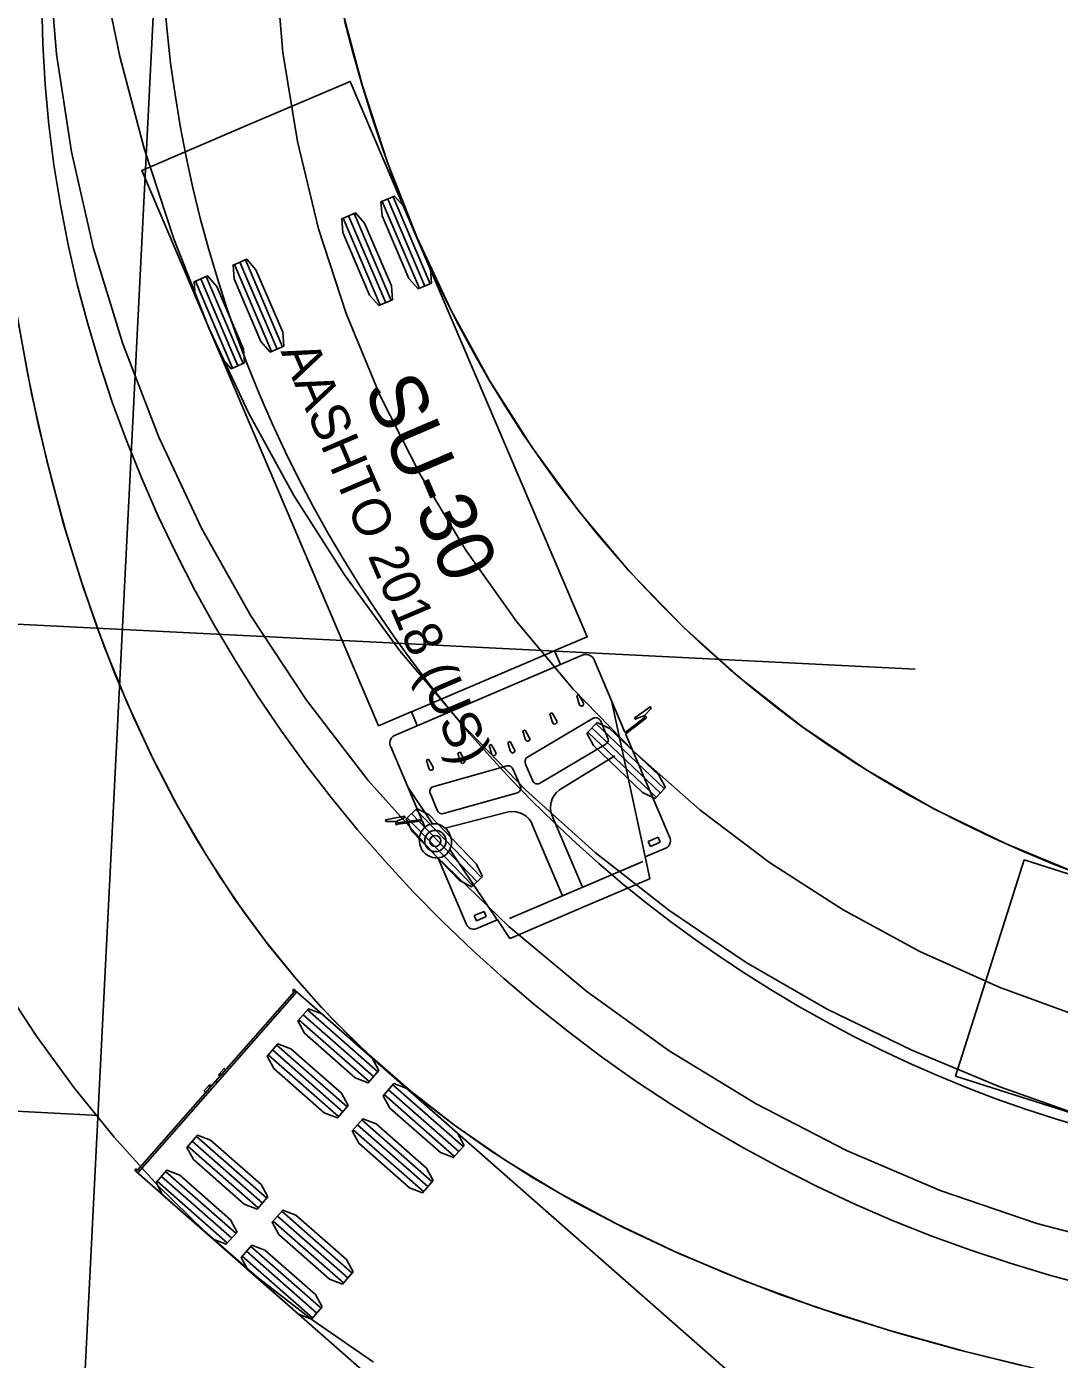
# Model space of a CAD drawing. Extents: x 260275 to 261282, y 610916 to 614143.
# Drawn here: x 261018.91 to 261055.33, y 611607.94 to 611654.93 of the extents above; entities that cross this region are included whole.
import ezdxf

# ---------------------------------------------------------------- set-up
doc = ezdxf.new("R2010")
doc.units = 0
for name, color, linetype in [('DR_P_Ditch', 7, 'Continuous'), ('GE_X_Alignment', 7, 'Continuous'), ('UT_X_Water_Cells', 7, 'Continuous')]:
    doc.layers.add(name, color=color, linetype=linetype)

msp = doc.modelspace()

# ---------------------------------------------------------------- linework, layer by layer
at = {"layer": 'DR_P_Ditch'}
msp.add_line((260830.144, 611626.697), (261021.455, 611616.54), dxfattribs=at)
at = {"layer": 'GE_X_Alignment'}
msp.add_line((260986.249, 610915.954), (261148.276, 614142.838), dxfattribs=at)
at = {"layer": 'UT_X_Water_Cells'}
for p, q in [((261032.763, 611645.701), (261031.455, 611648.767)), ((261032.955, 611645.783), (261031.646, 611648.849)), ((261033.146, 611645.865), (261031.838, 611648.931)), ((261031.767, 611645.276), (261030.458, 611648.342)), ((261031.383, 611645.113), (261030.075, 611648.178)), ((261031.575, 611645.194), (261030.267, 611648.26)), ((261027.551, 611643.477), (261026.243, 611646.543)), ((261027.743, 611643.559), (261026.434, 611646.625)), ((261027.934, 611643.641), (261026.626, 611646.706)), ((261026.172, 611642.888), (261024.863, 611645.954)), ((261026.363, 611642.97), (261025.055, 611646.036)), ((261026.555, 611643.052), (261025.246, 611646.118)), ((261050.252, 611632.276), (261008.305, 611634.382)), ((261032.48, 611630.772), (261037.531, 611632.928)), ((261032.688, 611630.283), (261037.739, 611632.439)), ((261038.314, 611631.336), (261038.39, 611631.368)), ((261038.39, 611631.368), (261038.54, 611631.107)), ((261038.399, 611631.046), (261038.314, 611631.336)), ((261039.537, 611631.167), (261040.728, 611625.664)), ((261036.571, 611629.174), (261038.911, 611630.555)), ((261037.369, 611630.704), (261037.445, 611630.736)), ((261037.46, 611630.402), (261037.369, 611630.704)), ((261037.445, 611630.736), (261037.602, 611630.462)), ((261039.157, 611630.44), (261039.399, 611629.873)), ((261036.413, 611630.098), (261036.489, 611630.13)), ((261036.498, 611629.808), (261036.413, 611630.098)), ((261036.489, 611630.13), (261036.64, 611629.868)), ((261041.119, 611627.76), (261038.704, 611630.058)), ((261041.262, 611627.91), (261038.848, 611630.209)), ((261041.406, 611628.061), (261038.991, 611630.359)), ((261035.221, 611629.589), (261035.296, 611629.621)), ((261035.305, 611629.299), (261035.221, 611629.589)), ((261035.296, 611629.621), (261035.447, 611629.359)), ((261035.883, 611629.688), (261035.959, 611629.721)), ((261035.967, 611629.398), (261035.883, 611629.688)), ((261035.959, 611629.721), (261036.109, 611629.459)), ((261039.339, 611629.628), (261036.999, 611628.247)), ((261033.011, 611629.073), (261033.087, 611629.105)), ((261033.096, 611628.783), (261033.011, 611629.073)), ((261033.087, 611629.105), (261033.238, 611628.843)), ((261034.121, 611629.318), (261034.197, 611629.35)), ((261034.206, 611629.028), (261034.121, 611629.318)), ((261034.197, 611629.35), (261034.348, 611629.089)), ((261037.707, 611628.02), (261039.654, 611629.226)), ((261035.854, 611628.868), (261033.238, 611628.134)), ((261036.315, 611628.174), (261036.073, 611628.742)), ((261036.753, 611628.361), (261036.51, 611628.928)), ((261032.363, 611628.105), (261033.23, 611626.821)), ((261033.15, 611627.877), (261033.393, 611627.309)), ((261033.611, 611627.183), (261036.227, 611627.917)), ((261034.798, 611624.781), (261032.487, 611627.184)), ((261034.948, 611624.926), (261032.638, 611627.329)), ((261035.901, 611627.249), (261033.672, 611626.675)), ((261034.647, 611624.637), (261032.337, 611627.04)), ((261037.816, 611624.288), (261036.769, 611626.742)), ((261038.52, 611624.589), (261037.473, 611627.043)), ((261040.834, 611626.205), (261041.183, 611626.354)), ((261040.911, 611626.027), (261040.834, 611626.205)), ((261041.183, 611626.354), (261041.259, 611626.175)), ((261033.837, 611625.921), (261035.512, 611623.438)), ((261041.259, 611626.175), (261040.911, 611626.027)), ((261033.424, 611625.619), (261034.414, 611623.299)), ((261035.943, 611623.489), (261040.638, 611625.492)), ((261035.048, 611623.736), (261034.699, 611623.587)), ((261034.699, 611623.587), (261034.776, 611623.409)), ((261034.776, 611623.409), (261035.124, 611623.557)), ((261035.124, 611623.557), (261035.048, 611623.736)), ((261022.829, 611614.518), (261028.44, 611620.904)), ((261031.149, 611617.913), (261028.67, 611620.091)), ((261031.3, 611618.085), (261028.821, 611620.264)), ((261030.998, 611617.741), (261028.518, 611619.919)), ((261029.909, 611616.502), (261027.429, 611618.68)), ((261030.06, 611616.674), (261027.581, 611618.852)), ((261030.211, 611616.846), (261027.732, 611619.024)), ((261025.753, 611617.952), (261025.407, 611617.559)), ((261025.582, 611617.757), (261025.635, 611617.711)), ((261025.757, 611617.957), (261025.932, 611618.156)), ((261025.231, 611617.358), (261025.406, 611617.558)), ((261034.003, 611615.101), (261031.523, 611617.279)), ((261034.154, 611615.273), (261031.675, 611617.451)), ((261034.305, 611615.445), (261031.826, 611617.623)), ((261033.216, 611614.206), (261030.737, 611616.384)), ((261032.913, 611613.861), (261030.434, 611616.04)), ((261033.065, 611614.034), (261030.586, 611616.212)), ((261027.081, 611613.284), (261024.602, 611615.462)), ((261027.233, 611613.456), (261024.754, 611615.634)), ((261027.384, 611613.628), (261024.905, 611615.806)), ((261026.295, 611612.389), (261023.816, 611614.567)), ((261025.992, 611612.044), (261023.513, 611614.222)), ((261026.144, 611612.216), (261023.664, 611614.395)), ((261030.389, 611610.988), (261027.91, 611613.166)), ((261030.086, 611610.644), (261027.607, 611612.822)), ((261030.238, 611610.816), (261027.758, 611612.994)), ((261029.149, 611609.576), (261026.669, 611611.754)), ((261029.3, 611609.748), (261026.821, 611611.927)), ((261028.997, 611609.404), (261026.518, 611611.582))]:
    msp.add_line(p, q, dxfattribs=at)
for points in [[(261019.685, 611657.393), (261019.965, 611653.952), (261020.495, 611650.516), (261021.274, 611647.106), (261022.301, 611643.744), (261023.571, 611640.451), (261025.079, 611637.247), (261026.82, 611634.151), (261028.783, 611631.182), (261030.961, 611628.357), (261033.342, 611625.694), (261035.914, 611623.208), (261038.663, 611620.913), (261041.576, 611618.823), (261044.636, 611616.95), (261047.827, 611615.306), (261051.133, 611613.899), (261054.534, 611612.738), (261058.013, 611611.83)], [(261027.678, 611657.213), (261027.951, 611654.015), (261028.463, 611650.874), (261029.209, 611647.801), (261030.183, 611644.811), (261031.378, 611641.918), (261032.786, 611639.134), (261034.396, 611636.474), (261036.2, 611633.95), (261038.186, 611631.575), (261040.342, 611629.361), (261042.656, 611627.319), (261045.114, 611625.459), (261047.702, 611623.79), (261050.406, 611622.322), (261053.21, 611621.06), (261056.099, 611620.012)], [(261021.521, 611657.179), (261022.202, 611653.88), (261023.06, 611650.632), (261024.1, 611647.448), (261025.326, 611644.339), (261026.738, 611641.319), (261028.336, 611638.402), (261030.118, 611635.599), (261032.078, 611632.926), (261034.21, 611630.395), (261036.507, 611628.018), (261038.96, 611625.808), (261041.559, 611623.777), (261044.291, 611621.936), (261047.145, 611620.294), (261050.133, 611618.839), (261053.236, 611617.552), (261056.422, 611616.419)], [(261056.385, 611610.538), (261054.985, 611610.914), (261053.592, 611611.332), (261052.208, 611611.791), (261050.834, 611612.291), (261049.472, 611612.833), (261048.123, 611613.417), (261046.788, 611614.041), (261045.47, 611614.706), (261044.169, 611615.411), (261042.89, 611616.155), (261041.632, 611616.936), (261040.399, 611617.755), (261039.191, 611618.609), (261038.011, 611619.497), (261036.859, 611620.419), (261035.736, 611621.374), (261034.643, 611622.362), (261033.581, 611623.381), (261032.55, 611624.43), (261031.552, 611625.508), (261030.587, 611626.615), (261029.657, 611627.749), (261028.763, 611628.909), (261027.904, 611630.095), (261027.083, 611631.304), (261026.299, 611632.536), (261025.554, 611633.79), (261024.848, 611635.063), (261024.182, 611636.356), (261023.557, 611637.667), (261022.973, 611638.995), (261022.432, 611640.338), (261021.933, 611641.695), (261021.478, 611643.064), (261021.066, 611644.445), (261020.7, 611645.836), (261020.379, 611647.235), (261020.103, 611648.642), (261019.875, 611650.055), (261019.694, 611651.472), (261019.563, 611652.892), (261019.48, 611654.314), (261019.448, 611655.737)], [(261029.995, 611655.687), (261030.74, 611652.873), (261031.635, 611650.135), (261032.684, 611647.48), (261033.885, 611644.915), (261035.237, 611642.449), (261036.738, 611640.091), (261038.382, 611637.85), (261040.166, 611635.735), (261042.082, 611633.755), (261044.124, 611631.919), (261046.281, 611630.235), (261048.546, 611628.711), (261050.908, 611627.354), (261053.428, 611626.129), (261056.118, 611625.015)], [(261030.125, 611655.149), (261030.416, 611654.02), (261030.731, 611652.902), (261031.071, 611651.796), (261031.435, 611650.703), (261031.823, 611649.623), (261032.236, 611648.557), (261032.673, 611647.504), (261033.135, 611646.466), (261033.621, 611645.443), (261034.132, 611644.435), (261034.666, 611643.444), (261035.225, 611642.469), (261035.807, 611641.512), (261036.413, 611640.573), (261037.042, 611639.652), (261037.695, 611638.75), (261038.369, 611637.867), (261039.066, 611637.005), (261039.785, 611636.163), (261040.525, 611635.343), (261041.286, 611634.545), (261042.068, 611633.769), (261042.87, 611633.016), (261043.691, 611632.287), (261044.531, 611631.582), (261045.39, 611630.901), (261046.266, 611630.246), (261047.16, 611629.616), (261048.073, 611629.01), (261049.005, 611628.429), (261049.959, 611627.872), (261050.936, 611627.34), (261051.935, 611626.831), (261052.958, 611626.343), (261054.003, 611625.876), (261055.07, 611625.429), (261056.161, 611624.999)], [(261038.566, 611632.792), (261037.742, 611632.44), (261037.738, 611632.442), (261037.531, 611632.927), (261037.541, 611632.932), (261038.684, 611633.42), (261030.328, 611652.998), (261026.649, 611651.428), (261022.971, 611649.858), (261031.326, 611630.28), (261032.469, 611630.768), (261032.48, 611630.771), (261032.687, 611630.286), (261032.685, 611630.282), (261031.861, 611629.93)], [(261018.578, 611644.761), (261018.933, 611642.78), (261019.336, 611640.855), (261019.785, 611638.988), (261020.279, 611637.179), (261020.819, 611635.43), (261021.402, 611633.742), (261022.028, 611632.117), (261022.694, 611630.556), (261023.399, 611629.059), (261024.141, 611627.628), (261024.918, 611626.263), (261025.726, 611624.964), (261026.564, 611623.733), (261027.435, 611622.56), (261028.348, 611621.437), (261029.312, 611620.352), (261030.341, 611619.296), (261031.448, 611618.262), (261032.638, 611617.25), (261033.916, 611616.261), (261035.288, 611615.297), (261036.756, 611614.361), (261038.32, 611613.456), (261039.98, 611612.587), (261041.735, 611611.756), (261043.581, 611610.967), (261045.513, 611610.224), (261047.527, 611609.527), (261049.617, 611608.878), (261051.777, 611608.279), (261054.001, 611607.729)], [(261018.628, 611644.458), (261019.089, 611642), (261019.623, 611639.63), (261020.229, 611637.351), (261020.905, 611635.166), (261021.65, 611633.078), (261022.459, 611631.088), (261023.331, 611629.198), (261024.26, 611627.411), (261025.242, 611625.728), (261026.272, 611624.149), (261027.346, 611622.676), (261028.465, 611621.299), (261029.678, 611619.965), (261031.004, 611618.664), (261032.457, 611617.397), (261034.049, 611616.164), (261035.787, 611614.968), (261037.677, 611613.817), (261039.72, 611612.717), (261041.913, 611611.676), (261044.247, 611610.702), (261046.716, 611609.798), (261049.308, 611608.97), (261052.011, 611608.218), (261054.813, 611607.544)], [(261040.688, 611630.564), (261040.688, 611630.564), (261040.023, 611630.041), (261040.014, 611630.05), (261038.925, 611632.602)], [(261040.731, 611630.61), (261040.713, 611630.654), (261040.713, 611630.654), (261040.933, 611630.891), (261040.907, 611630.951), (261040.905, 611630.949), (261040.356, 611630.564), (261040.354, 611630.562), (261040.376, 611630.511), (261040.378, 611630.511), (261040.673, 611630.628), (261040.674, 611630.628), (261040.691, 611630.587)], [(261041.588, 611626.361), (261040.044, 611629.978), (261040.046, 611629.992), (261040.722, 611630.527), (261040.723, 611630.527)], [(261031.751, 611629.54), (261032.84, 611626.988), (261032.84, 611626.975), (261032.002, 611626.857), (261032.002, 611626.857)], [(261031.984, 611626.871), (261031.966, 611626.911), (261031.966, 611626.912), (261032.254, 611627.044), (261032.257, 611627.045), (261032.235, 611627.097), (261032.232, 611627.096), (261031.574, 611626.967), (261031.571, 611626.966), (261031.597, 611626.906), (261031.919, 611626.901), (261031.92, 611626.901), (261031.939, 611626.858)], [(261032.005, 611626.806), (261032.006, 611626.807), (261032.859, 611626.925), (261032.87, 611626.917), (261032.96, 611626.707)], [(261034.766, 611623.12), (261035.509, 611623.437), (261035.515, 611623.435), (261035.954, 611622.783), (261035.994, 611622.798), (261038.425, 611623.836), (261040.857, 611624.873), (261040.895, 611624.892), (261040.729, 611625.66), (261040.731, 611625.666), (261041.474, 611625.983)], [(261074.781, 611618.598), (261074.509, 611617.744), (261074.505, 611617.743), (261074.003, 611617.902), (261074.005, 611617.913), (261074.382, 611619.098), (261054.096, 611625.549), (261052.884, 611621.737), (261051.672, 611617.925), (261071.957, 611611.474), (261072.334, 611612.658), (261072.338, 611612.669), (261072.84, 611612.509), (261072.843, 611612.505), (261072.571, 611611.651)], [(261017.997, 611621.282), (261019.262, 611619.342), (261020.595, 611617.511), (261022.001, 611615.78), (261023.534, 611614.091), (261025.21, 611612.445), (261027.035, 611610.851), (261029.013, 611609.316), (261031.146, 611607.847)], [(261022.791, 611614.581), (261022.776, 611614.565), (261058.783, 611582.93), (261061.588, 611586.122), (261064.393, 611589.315), (261028.387, 611620.95), (261028.372, 611620.933)], [(261028.356, 611620.915), (261028.355, 611620.914), (261025.956, 611618.183), (261025.932, 611618.157), (261025.88, 611618.203), (261025.878, 611618.202), (261025.703, 611618.002)], [(261025.355, 611617.606), (261025.179, 611617.406), (261025.178, 611617.405), (261025.231, 611617.358), (261025.207, 611617.331), (261022.808, 611614.6), (261022.807, 611614.6)]]:
    msp.add_lwpolyline(points, dxfattribs=at)
for points in [[(261033.194, 611645.885), (261032.716, 611645.681), (261032.388, 611646.049), (261031.446, 611648.256), (261031.407, 611648.747), (261031.885, 611648.951), (261032.213, 611648.583), (261033.155, 611646.376)], [(261031.814, 611645.296), (261031.336, 611645.092), (261031.009, 611645.46), (261030.067, 611647.667), (261030.027, 611648.158), (261030.506, 611648.362), (261030.833, 611647.994), (261031.775, 611645.787)], [(261027.982, 611643.661), (261027.504, 611643.457), (261027.176, 611643.824), (261026.234, 611646.032), (261026.195, 611646.523), (261026.673, 611646.727), (261027.001, 611646.359), (261027.943, 611644.152)], [(261026.602, 611643.072), (261026.124, 611642.868), (261025.797, 611643.236), (261024.855, 611645.443), (261024.816, 611645.934), (261025.294, 611646.138), (261025.621, 611645.77), (261026.563, 611643.563)], [(261041.442, 611628.099), (261041.083, 611627.722), (261040.637, 611627.93), (261038.899, 611629.585), (261038.669, 611630.02), (261039.027, 611630.397), (261039.473, 611630.189), (261041.212, 611628.534)], [(261034.985, 611624.962), (261034.61, 611624.601), (261034.174, 611624.829), (261032.51, 611626.559), (261032.3, 611627.004), (261032.675, 611627.365), (261033.111, 611627.137), (261034.774, 611625.407)], [(261031.338, 611618.128), (261030.96, 611617.698), (261030.499, 611617.874), (261028.714, 611619.442), (261028.481, 611619.877), (261028.859, 611620.306), (261029.319, 611620.131), (261031.104, 611618.563)], [(261030.249, 611616.889), (261029.871, 611616.459), (261029.41, 611616.634), (261027.625, 611618.203), (261027.392, 611618.637), (261027.769, 611619.067), (261028.23, 611618.891), (261030.015, 611617.323)], [(261034.343, 611615.488), (261033.965, 611615.058), (261033.504, 611615.234), (261031.719, 611616.802), (261031.486, 611617.236), (261031.863, 611617.666), (261032.324, 611617.491), (261034.109, 611615.922)], [(261033.253, 611614.248), (261032.876, 611613.819), (261032.415, 611613.994), (261030.63, 611615.562), (261030.397, 611615.997), (261030.774, 611616.427), (261031.235, 611616.251), (261033.02, 611614.683)], [(261027.421, 611613.671), (261027.044, 611613.241), (261026.583, 611613.417), (261024.798, 611614.985), (261024.565, 611615.419), (261024.942, 611615.849), (261025.403, 611615.673), (261027.188, 611614.105)], [(261026.332, 611612.431), (261025.955, 611612.002), (261025.494, 611612.177), (261023.709, 611613.745), (261023.476, 611614.18), (261023.853, 611614.609), (261024.314, 611614.434), (261026.099, 611612.866)], [(261030.426, 611611.031), (261030.049, 611610.601), (261029.588, 611610.776), (261027.803, 611612.345), (261027.57, 611612.779), (261027.947, 611613.209), (261028.408, 611613.033), (261030.193, 611611.465)], [(261029.337, 611609.791), (261028.96, 611609.361), (261028.499, 611609.537), (261026.714, 611611.105), (261026.481, 611611.54), (261026.858, 611611.969), (261027.319, 611611.794), (261029.104, 611610.226)]]:
    msp.add_lwpolyline(points, close=True, dxfattribs=at)
for centre, radius in [((261033.325, 611626.22), 0.374), ((261033.325, 611626.22), 0.193), ((261028.338, 611620.947), 0.0266), ((261022.773, 611614.613), 0.0266)]:
    msp.add_circle(centre, radius, dxfattribs=at)
for centre, radius, start, end in [((261068.634, 611659.376), 45, 177.1255, 267.0825), ((261038.628, 611632.475), 0.323, 23.112, 100.9604), ((261038.488, 611631.064), 0.0909, 191.3929, 285.6281), ((261038.466, 611631.055), 0.091, 300.6316, 34.7955), ((261037.521, 611630.423), 0.091, 300.6316, 34.7955), ((261038.981, 611630.384), 0.184, 17.6482, 112.5195), ((261040.731, 611630.571), 0.0434, 158.5257, 189.1985), ((261040.726, 611630.569), 0.0418, 265.6039, 82.6189), ((261037.543, 611630.432), 0.0909, 191.3929, 285.6281), ((261032.047, 611629.667), 0.323, 125.2636, 203.112), ((261036.587, 611629.826), 0.0909, 191.3929, 285.6281), ((261036.565, 611629.816), 0.091, 300.6316, 34.7955), ((261039.228, 611629.785), 0.193, 305.2544, 27.1689), ((261034.295, 611629.046), 0.091, 191.4286, 285.5925), ((261034.273, 611629.037), 0.0909, 300.5959, 34.8311), ((261035.394, 611629.317), 0.091, 191.4286, 285.5925), ((261035.372, 611629.307), 0.0909, 300.5959, 34.8311), ((261036.057, 611629.416), 0.091, 191.4286, 285.5925), ((261036.035, 611629.407), 0.091, 300.6316, 34.7955), ((261036.682, 611629.016), 0.193, 125.2495, 207.1739), ((261033.185, 611628.801), 0.091, 191.4286, 285.5925), ((261033.163, 611628.792), 0.0909, 300.5959, 34.8311), ((261035.891, 611628.679), 0.193, 19.0502, 100.9745), ((261033.312, 611627.965), 0.184, 113.7046, 208.5759), ((261036.153, 611628.086), 0.184, 293.7102, 28.5703), ((261036.928, 611628.417), 0.184, 197.6538, 292.5139), ((261038.161, 611627.395), 0.773, 126.0025, 207.0867), ((261033.575, 611627.372), 0.193, 199.0551, 280.9696), ((261036.039, 611626.489), 0.773, 19.1374, 100.2216), ((261052.872, 611624.635), 42, 177.1255, 293.7992), ((261031.973, 611626.833), 0.0418, 143.6052, 320.6201), ((261031.967, 611626.831), 0.0434, 37.0255, 67.6983), ((261033.387, 611626.246), 0.628, 132.8653, 273.357), ((261033.291, 611626.3), 0.524, 75.371, 129.1711), ((261033.259, 611626.199), 0.63, 22.4668, 74.8696), ((261033.266, 611626.186), 0.629, 335.1576, 23.8469), ((261041.339, 611626.23), 0.282, 298.6604, 27.7399), ((261033.359, 611626.141), 0.526, 277.0572, 335.3032), ((261034.681, 611623.389), 0.282, 198.4842, 287.5636), ((261028.338, 611620.947), 0.0363, 337.7745, 298.9371), ((261025.729, 611617.979), 0.0352, 138.7132, 319.2997), ((261025.729, 611617.979), 0.0352, 318.4852, 141.1246), ((261025.381, 611617.583), 0.0354, 142.9892, 315.1747), ((261025.381, 611617.583), 0.0352, 318.0956, 138.6821), ((261022.773, 611614.613), 0.0363, 338.4582, 299.6209)]:
    msp.add_arc(centre, radius, start, end, dxfattribs=at)

# ---------------------------------------------------------------- texts
for s, height, p in [('AASHTO 2018 (US)', 1.33333, (261027.86, 611643.479)), ('SU-30', 2, (261030.778, 611642.162))]:
    msp.add_text(s, height=height, rotation=293.112, dxfattribs=at).set_placement(p)

doc.saveas('drawing.dxf')
